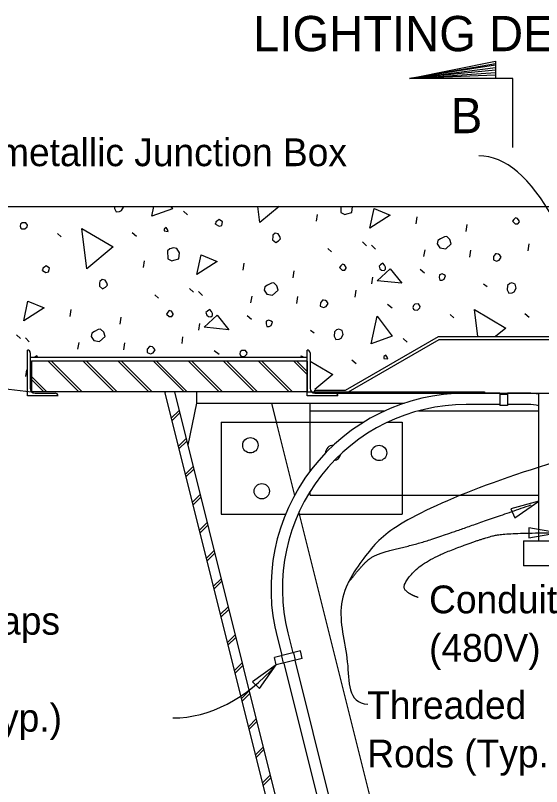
# Model space of a CAD drawing. Extents: x 112544 to 112597.1, y 111084 to 111107.1.
# Drawn here: x 112545.622 to 112548.485, y 111091.281 to 111095.48 of the extents above; entities that cross this region are included whole.
import ezdxf

# ---------------------------------------------------------------- set-up
doc = ezdxf.new("R2010")
doc.units = 0
for name, color, linetype in [('Dimension', 7, 'Continuous'), ('Lighting', 7, 'Continuous'), ('Miscellaneous', 7, 'Continuous'), ('SteelGirder', 7, 'Continuous'), ('SteelGirder_h', 7, 'Continuous'), ('SupstrConc', 7, 'Continuous'), ('TextStructures', 7, 'Continuous')]:
    doc.layers.add(name, color=color, linetype=linetype)

msp = doc.modelspace()

# ---------------------------------------------------------------- linework, layer by layer
at = {"layer": 'Dimension'}
for p, q in [((112547.7665, 111095.1362), (112548.2352, 111095.2187)), ((112548.2352, 111095.2087), (112547.7665, 111095.1362)), ((112547.7665, 111095.1362), (112548.2352, 111095.1962)), ((112548.2352, 111095.1824), (112547.7665, 111095.1362)), ((112547.7665, 111095.1362), (112548.2352, 111095.1687)), ((112548.2352, 111095.1537), (112547.7665, 111095.1362))]:
    msp.add_line(p, q, dxfattribs=at)
msp.add_lwpolyline([(112548.3289, 111094.7612), (112548.3289, 111095.1362), (112547.7665, 111095.1362), (112548.2352, 111095.2299), (112548.2352, 111095.1362)], dxfattribs=at)
for points in [[(112548.4699, 111092.8343), (112548.317, 111092.7931), (112548.3391, 111092.745)], [(112548.5722, 111092.6627), (112548.416, 111092.6892), (112548.416, 111092.6362)], [(112547.0411, 111091.9439), (112546.9118, 111091.8524), (112546.9491, 111091.8149)]]:
    msp.add_lwpolyline(points, close=True, dxfattribs=at)
for centre, major_axis, ratio, start_param, end_param in [((112548.1769, 111092.198), (0.0332, -2.5173), 0.313255, 2.075166, 3.141607), ((112546.4637, 111093.2488), (-0.0144, 1.5941), 0.622544, 3.141613, 3.747853)]:
    msp.add_ellipse(centre, major_axis=major_axis, ratio=ratio, start_param=start_param, end_param=end_param, dxfattribs=at)
for points, degree in [([(112548.9701, 111093.1717), (112548.6743, 111093.0852), (112548.1844, 111092.9372), (112547.674, 111092.7074), (112547.5362, 111092.5593), (112547.3473, 111092.2836), (112547.4514, 111091.9614), (112547.4271, 111091.7394), (112547.5394, 111091.7292)], 3), ([(112547.4342, 111092.3931), (112547.5004, 111092.4776), (112547.577, 111092.5491), (112547.8271, 111092.6053), (112548.0874, 111092.6972), (112548.4279, 111092.8149)], 2), ([(112547.8143, 111092.3104), (112547.7556, 111092.3308), (112547.725, 111092.3819), (112547.85, 111092.5146), (112548.1741, 111092.6372), (112548.2992, 111092.6627), (112548.5722, 111092.6627)], 2), ([(112546.6152, 111090.8361), (112548.0879, 111090.8463), (112549.0316, 111090.8974), (112549.0112, 111091.3926), (112548.9755, 111092.3627)], 2)]:
    msp.add_open_spline(points, degree=degree, dxfattribs=at)
at = {"layer": 'Lighting'}
for p, q in [((112548.2588, 111093.4236), (112548.0748, 111093.4236)), ((112548.4112, 111093.4236), (112548.3005, 111093.4236)), ((112548.2588, 111093.3611), (112548.0748, 111093.3611)), ((112548.4115, 111093.3611), (112548.3005, 111093.3611)), ((112548.3866, 111092.6185), (112549.0845, 111092.6185)), ((112548.3866, 111092.6185), (112548.3866, 111092.4831)), ((112548.5971, 111092.4831), (112548.3866, 111092.4831)), ((112547.0475, 111092.0902), (112547.0714, 111091.9945)), ((112547.1047, 111092.1186), (112547.1319, 111092.0096)), ((112547.0815, 111091.954), (112547.5799, 111089.9602)), ((112547.142, 111091.9692), (112547.6405, 111089.9754))]:
    msp.add_line(p, q, dxfattribs=at)
for centre, radius, start, end in [((112548.0748, 111092.3611), 1.0625, 90.0002, 194.7729), ((112548.4109, 111093.1111), 0.3125, 79.1097, 89.9466), ((112548.0748, 111092.3611), 1, 90.0002, 194.0354), ((112548.4109, 111093.1111), 0.25, 76.3399, 89.8674)]:
    msp.add_arc(centre, radius, start, end, dxfattribs=at)
at = {"layer": 'Miscellaneous'}
for p, q in [((112546.5366, 111094.4148), (112546.5576, 111094.3946)), ((112547.2604, 111094.3603), (112547.2665, 111094.3956)), ((112547.8028, 111094.3452), (112547.8082, 111094.3829)), ((112548.0752, 111094.3043), (112548.0806, 111094.342)), ((112545.8498, 111094.2929), (112545.8701, 111094.2751)), ((112546.2572, 111094.2986), (112546.2806, 111094.2789)), ((112547.511, 111094.2463), (112547.5319, 111094.226)), ((112547.5598, 111094.2283), (112547.5807, 111094.208)), ((112548.4117, 111094.1978), (112548.4171, 111094.2354)), ((112547.3211, 111094.2109), (112547.3414, 111094.1931)), ((112547.8452, 111094.1676), (112547.8513, 111094.2029)), ((112548.0945, 111094.1645), (112548.0999, 111094.2022)), ((112546.3186, 111094.108), (112546.3247, 111094.1432)), ((112546.861, 111094.0928), (112546.8665, 111094.1305)), ((112547.8252, 111094.0975), (112547.8485, 111094.0779)), ((112547.1334, 111094.0519), (112547.1388, 111094.0896)), ((112547.5615, 111094.0191), (112547.5675, 111094.0544)), ((112548.1697, 111094.019), (112548.1894, 111094.0036)), ((112546.5692, 111093.9939), (112546.5901, 111093.9737)), ((112546.618, 111093.9759), (112546.639, 111093.9557)), ((112547.4699, 111093.9454), (112547.4754, 111093.9831)), ((112546.3794, 111093.9586), (112546.3997, 111093.9407)), ((112546.9034, 111093.9153), (112546.9095, 111093.9505)), ((112547.1527, 111093.9122), (112547.1582, 111093.9499)), ((112547.6458, 111093.9071), (112547.6716, 111093.8882)), ((112545.9192, 111093.8405), (112545.9247, 111093.8782)), ((112546.8834, 111093.8452), (112546.9068, 111093.8256)), ((112547.987, 111093.851), (112548.0073, 111093.8332)), ((112548.3944, 111093.8566), (112548.4178, 111093.837)), ((112546.1916, 111093.7996), (112546.197, 111093.8373)), ((112546.6197, 111093.7668), (112546.6258, 111093.802)), ((112547.2279, 111093.7667), (112547.2476, 111093.7512)), ((112545.6274, 111093.7416), (112545.6484, 111093.7213)), ((112545.6762, 111093.7236), (112545.6972, 111093.7033)), ((112546.5282, 111093.6931), (112546.5336, 111093.7307)), ((112547.4182, 111093.4392), (112547.9235, 111093.7309)), ((112547.732, 111093.7206), (112547.753, 111093.7003)), ((112547.9235, 111093.7309), (112552.7436, 111093.7309)), ((112545.9617, 111093.6629), (112545.9677, 111093.6982)), ((112546.2109, 111093.6598), (112546.2164, 111093.6975)), ((112547.4224, 111093.4236), (112547.9277, 111093.7153)), ((112547.9277, 111093.7153), (112552.7436, 111093.7153)), ((112545.6866, 111093.4079), (112545.6866, 111093.6579)), ((112545.7022, 111093.6423), (112545.7022, 111093.4496)), ((112546.7041, 111093.6548), (112546.7298, 111093.6358)), ((112547.2099, 111093.408), (112547.2099, 111093.658)), ((112547.2256, 111093.6423), (112547.2255, 111093.4496)), ((112545.7023, 111093.6187), (112547.2099, 111093.6187)), ((112545.7023, 111093.5979), (112545.7099, 111093.5979)), ((112545.9664, 111093.4312), (112545.7997, 111093.5979)), ((112545.9841, 111093.4312), (112545.8173, 111093.5979)), ((112546.1573, 111093.4312), (112545.9906, 111093.5979)), ((112546.175, 111093.4312), (112546.0083, 111093.5979)), ((112546.3482, 111093.4312), (112546.1815, 111093.5979)), ((112546.3659, 111093.4312), (112546.1992, 111093.5979)), ((112546.5391, 111093.4312), (112546.3724, 111093.5979)), ((112546.5568, 111093.4312), (112546.3901, 111093.5979)), ((112546.7301, 111093.4312), (112546.5633, 111093.5979)), ((112546.7477, 111093.4312), (112546.581, 111093.5979)), ((112546.921, 111093.4312), (112546.7543, 111093.5979)), ((112546.9387, 111093.4312), (112546.7719, 111093.5979)), ((112547.1119, 111093.4312), (112546.9452, 111093.5979)), ((112547.1296, 111093.4312), (112546.9629, 111093.5979)), ((112547.2099, 111093.5241), (112547.1361, 111093.5979)), ((112547.2099, 111093.5418), (112547.1538, 111093.5979)), ((112547.4526, 111093.6043), (112547.476, 111093.5847)), ((112545.6779, 111093.5144), (112545.684, 111093.5497)), ((112545.7931, 111093.4312), (112545.7099, 111093.5144)), ((112545.7755, 111093.4312), (112545.7099, 111093.4968)), ((112545.7283, 111093.4235), (112545.8376, 111093.4235)), ((112546.4345, 111093.425), (112546.4407, 111093.4311)), ((112547.2516, 111093.4392), (112547.4182, 111093.4392)), ((112547.2516, 111093.4236), (112547.2516, 111093.4392)), ((112547.2516, 111093.4236), (112547.361, 111093.4236)), ((112547.2516, 111093.4236), (112552.7436, 111093.4236)), ((112545.8533, 111093.4079), (112545.6866, 111093.4079)), ((112547.3766, 111093.4079), (112547.2099, 111093.408)), ((112546.4692, 111093.2864), (112546.5121, 111093.3294)), ((112546.4727, 111093.2723), (112546.5157, 111093.3153)), ((112546.5074, 111093.1337), (112546.5503, 111093.1767)), ((112546.5109, 111093.1196), (112546.5539, 111093.1625)), ((112546.5456, 111092.981), (112546.5885, 111093.0239)), ((112546.5491, 111092.9668), (112546.5921, 111093.0098)), ((112546.5837, 111092.8282), (112546.6267, 111092.8712)), ((112546.5873, 111092.8141), (112546.6302, 111092.857)), ((112546.6219, 111092.6755), (112546.6649, 111092.7185)), ((112546.6255, 111092.6613), (112546.6684, 111092.7043)), ((112546.6601, 111092.5228), (112546.7031, 111092.5657)), ((112546.6636, 111092.5086), (112546.7066, 111092.5516)), ((112546.6983, 111092.37), (112546.7412, 111092.413)), ((112546.7018, 111092.3559), (112546.7448, 111092.3988)), ((112546.7365, 111092.2173), (112546.7794, 111092.2602)), ((112546.74, 111092.2031), (112546.783, 111092.2461)), ((112546.7747, 111092.0645), (112546.8176, 111092.1075)), ((112546.7782, 111092.0504), (112546.8212, 111092.0934)), ((112546.8128, 111091.9118), (112546.8558, 111091.9548)), ((112546.8164, 111091.8977), (112546.8593, 111091.9406)), ((112546.851, 111091.7591), (112546.894, 111091.802)), ((112546.8546, 111091.7449), (112546.8975, 111091.7879)), ((112546.8892, 111091.6063), (112546.9322, 111091.6493)), ((112546.8927, 111091.5922), (112546.9357, 111091.6352)), ((112546.9274, 111091.4536), (112546.9704, 111091.4966)), ((112546.9309, 111091.4395), (112546.9739, 111091.4824)), ((112546.9656, 111091.3009), (112547.0085, 111091.3438)), ((112546.9691, 111091.2867), (112547.0121, 111091.3297))]:
    msp.add_line(p, q, dxfattribs=at)
for points in [[(112546.1611, 111094.4392), (112546.1604, 111094.4279), (112546.1704, 111094.4099), (112546.188, 111094.412), (112546.1994, 111094.4177), (112546.21, 111094.436), (112546.2092, 111094.4392)], [(112546.3631, 111094.3865), (112546.3742, 111094.4392)], [(112546.4675, 111094.4392), (112546.4764, 111094.4272), (112546.3631, 111094.3865)], [(112546.9519, 111094.3527), (112546.9409, 111094.4392)], [(112547.0567, 111094.4392), (112546.9519, 111094.3527)], [(112547.392, 111094.4392), (112547.393, 111094.4062), (112547.4138, 111094.3962), (112547.4259, 111094.3995), (112547.4525, 111094.4066), (112547.4568, 111094.4388), (112547.4566, 111094.4392)], [(112547.5503, 111094.3215), (112547.5734, 111094.4286), (112547.6607, 111094.3925), (112547.5503, 111094.3215)], [(112545.6504, 111094.3223), (112545.6565, 111094.3188), (112545.6723, 111094.3178), (112545.6848, 111094.329), (112545.6877, 111094.3375), (112545.679, 111094.3507), (112545.6584, 111094.3503), (112545.65, 111094.3429), (112545.6478, 111094.332), (112545.6504, 111094.3223)], [(112546.7113, 111094.3426), (112546.7297, 111094.332), (112546.7441, 111094.3359), (112546.7493, 111094.3554), (112546.7303, 111094.3684), (112546.7219, 111094.361), (112546.7129, 111094.356), (112546.7113, 111094.3426), (112546.71, 111094.3474)], [(112548.3271, 111094.3589), (112548.3413, 111094.3445), (112548.3565, 111094.346), (112548.3642, 111094.3558), (112548.3629, 111094.3607), (112548.3542, 111094.3739), (112548.3426, 111094.3785), (112548.3348, 111094.3687), (112548.3271, 111094.3589)], [(112546.0101, 111094.1003), (112545.9821, 111094.3206), (112546.1542, 111094.2192), (112546.0101, 111094.1003)], [(112546.4311, 111094.3063), (112546.4524, 111094.3043), (112546.4498, 111094.3139), (112546.4417, 111094.3247), (112546.4309, 111094.3166), (112546.4311, 111094.3063)], [(112547.0217, 111094.2756), (112547.0214, 111094.2574), (112547.038, 111094.2438), (112547.0536, 111094.2531), (112547.0637, 111094.2636), (112547.0605, 111094.2757), (112547.0511, 111094.2913), (112547.0347, 111094.2947), (112547.0222, 111094.2835), (112547.0217, 111094.2756)], [(112547.9174, 111094.2361), (112547.9311, 111094.2139), (112547.9634, 111094.2096), (112547.9926, 111094.2356), (112547.9862, 111094.2597), (112547.9689, 111094.2758), (112547.9562, 111094.275), (112547.9358, 111094.2643), (112547.9201, 111094.255), (112547.9174, 111094.2361)], [(112546.4499, 111094.1975), (112546.4513, 111094.1539), (112546.4721, 111094.1439), (112546.4841, 111094.1471), (112546.5107, 111094.1542), (112546.515, 111094.1865), (112546.5006, 111094.2111), (112546.4818, 111094.2138), (112546.4625, 111094.2086), (112546.4499, 111094.1975)], [(112548.223, 111094.1679), (112548.2227, 111094.1497), (112548.2404, 111094.1415), (112548.2543, 111094.1478), (112548.2655, 111094.1638), (112548.2575, 111094.1745), (112548.2507, 111094.1805), (112548.2397, 111094.1827), (112548.2349, 111094.1814), (112548.223, 111094.1679)], [(112546.6085, 111094.0692), (112546.6316, 111094.1763), (112546.7189, 111094.1402), (112546.6085, 111094.0692)], [(112545.7695, 111094.0902), (112545.7879, 111094.0796), (112545.8024, 111094.0835), (112545.8075, 111094.103), (112545.7885, 111094.116), (112545.7801, 111094.1086), (112545.7711, 111094.1036), (112545.7695, 111094.0902), (112545.7682, 111094.0951)], [(112547.3854, 111094.1065), (112547.3995, 111094.0922), (112547.4147, 111094.0937), (112547.4224, 111094.1035), (112547.4211, 111094.1083), (112547.4124, 111094.1215), (112547.4008, 111094.1262), (112547.3931, 111094.1163), (112547.3854, 111094.1065)], [(112547.5909, 111094.0348), (112547.6614, 111094.1002), (112547.724, 111094.0212), (112547.5909, 111094.0348)], [(112547.6044, 111094.1005), (112547.6142, 111094.0928), (112547.6276, 111094.0912), (112547.6359, 111094.0986), (112547.6358, 111094.1089), (112547.6301, 111094.1203), (112547.622, 111094.1311), (112547.6089, 111094.1224), (112547.6005, 111094.115), (112547.6044, 111094.1005)], [(112547.9278, 111094.0526), (112547.9317, 111094.0381), (112547.9444, 111094.0389), (112547.9558, 111094.0445), (112547.9616, 111094.0616), (112547.9548, 111094.0676), (112547.9432, 111094.0722), (112547.9287, 111094.0683), (112547.9278, 111094.0526)], [(112546.0799, 111094.0233), (112546.0796, 111094.0051), (112546.0962, 111093.9914), (112546.1118, 111094.0008), (112546.122, 111094.0113), (112546.1187, 111094.0233), (112546.1094, 111094.0389), (112546.0929, 111094.0423), (112546.0804, 111094.0312), (112546.0799, 111094.0233)], [(112546.9757, 111093.9838), (112546.9894, 111093.9616), (112547.0216, 111093.9573), (112547.0509, 111093.9832), (112547.0444, 111094.0074), (112547.0271, 111094.0235), (112547.0144, 111094.0226), (112546.994, 111094.012), (112546.9784, 111094.0026), (112546.9757, 111093.9838)], [(112548.299, 111094.0097), (112548.2976, 111093.986), (112548.3076, 111093.968), (112548.3252, 111093.9701), (112548.3366, 111093.9757), (112548.3472, 111093.9941), (112548.3414, 111094.0159), (112548.3237, 111094.024), (112548.3116, 111094.0208), (112548.299, 111094.0097)], [(112547.2812, 111093.9155), (112547.2809, 111093.8973), (112547.2987, 111093.8892), (112547.3125, 111093.8955), (112547.3237, 111093.9114), (112547.3157, 111093.9222), (112547.3089, 111093.9281), (112547.298, 111093.9304), (112547.2931, 111093.9291), (112547.2812, 111093.9155)], [(112545.6668, 111093.8168), (112545.6898, 111093.9239), (112545.7772, 111093.8878), (112545.6668, 111093.8168)], [(112547.7876, 111093.8804), (112547.7937, 111093.8769), (112547.8095, 111093.8759), (112547.822, 111093.887), (112547.8249, 111093.8956), (112547.8162, 111093.9088), (112547.7956, 111093.9084), (112547.7872, 111093.901), (112547.785, 111093.8901), (112547.7876, 111093.8804)], [(112546.4436, 111093.8542), (112546.4578, 111093.8398), (112546.4729, 111093.8413), (112546.4806, 111093.8511), (112546.4793, 111093.856), (112546.4706, 111093.8692), (112546.459, 111093.8738), (112546.4513, 111093.864), (112546.4436, 111093.8542)], [(112546.6491, 111093.7824), (112546.7196, 111093.8479), (112546.7822, 111093.7689), (112546.6491, 111093.7824)], [(112546.6626, 111093.8481), (112546.6724, 111093.8404), (112546.6858, 111093.8388), (112546.6942, 111093.8462), (112546.694, 111093.8565), (112546.6883, 111093.868), (112546.6803, 111093.8788), (112546.6671, 111093.87), (112546.6587, 111093.8626), (112546.6626, 111093.8481)], [(112547.5585, 111093.6922), (112547.5905, 111093.8431), (112547.6718, 111093.7329), (112547.5585, 111093.6922)], [(112548.1381, 111093.7309), (112548.1193, 111093.8787), (112548.2914, 111093.7773), (112548.2351, 111093.7309)], [(112546.986, 111093.8002), (112546.9899, 111093.7857), (112547.0026, 111093.7865), (112547.014, 111093.7922), (112547.0198, 111093.8093), (112547.0131, 111093.8152), (112547.0015, 111093.8199), (112546.987, 111093.816), (112546.986, 111093.8002)], [(112546.0339, 111093.7314), (112546.0476, 111093.7092), (112546.0798, 111093.7049), (112546.1091, 111093.7309), (112546.1026, 111093.755), (112546.0854, 111093.7711), (112546.0726, 111093.7703), (112546.0522, 111093.7596), (112546.0366, 111093.7503), (112546.0339, 111093.7314)], [(112547.3573, 111093.7573), (112547.3558, 111093.7337), (112547.3659, 111093.7156), (112547.3834, 111093.7178), (112547.3948, 111093.7234), (112547.4054, 111093.7418), (112547.3996, 111093.7635), (112547.3819, 111093.7717), (112547.3698, 111093.7685), (112547.3573, 111093.7573)], [(112546.3394, 111093.6632), (112546.3391, 111093.645), (112546.3569, 111093.6368), (112546.3707, 111093.6431), (112546.382, 111093.6591), (112546.3739, 111093.6698), (112546.3671, 111093.6758), (112546.3562, 111093.678), (112546.3513, 111093.6767), (112546.3394, 111093.6632)], [(112546.8458, 111093.6281), (112546.8519, 111093.6245), (112546.8677, 111093.6236), (112546.8803, 111093.6347), (112546.8831, 111093.6432), (112546.8744, 111093.6564), (112546.8538, 111093.6561), (112546.8455, 111093.6487), (112546.8432, 111093.6377), (112546.8458, 111093.6281)], [(112545.7443, 111093.6187), (112545.7385, 111093.6264), (112545.7268, 111093.6187)], [(112547.1785, 111093.6187), (112547.1775, 111093.6264), (112547.1906, 111093.6187)], [(112547.2256, 111093.5981), (112547.3497, 111093.5249), (112547.2506, 111093.4433)], [(112547.6265, 111093.6121), (112547.6478, 111093.61), (112547.6452, 111093.6197), (112547.6371, 111093.6304), (112547.6264, 111093.6224), (112547.6265, 111093.6121)]]:
    msp.add_lwpolyline(points, dxfattribs=at)
for centre, radius, start, end in [((112545.6866, 111093.6423), 0.0156, 359.9953, 89.9953), ((112547.2099, 111093.6423), 0.0156, 359.9953, 89.9953), ((112545.7283, 111093.4496), 0.026, 179.9953, 269.9953), ((112545.8376, 111093.4079), 0.0156, 359.9953, 89.9953), ((112547.2516, 111093.4496), 0.026, 179.9953, 269.9953), ((112547.361, 111093.4079), 0.0156, 359.9953, 89.9953)]:
    msp.add_arc(centre, radius, start, end, dxfattribs=at)
at = {"layer": 'SteelGirder'}
for p, q in [((112545.7099, 111093.5979), (112545.7099, 111093.4311)), ((112547.2099, 111093.5979), (112545.7099, 111093.5979)), ((112547.2099, 111093.5979), (112547.2099, 111093.4311)), ((112547.2099, 111093.4311), (112545.7099, 111093.4311)), ((112546.433, 111093.4311), (112547.9955, 111087.1812)), ((112546.4867, 111093.4311), (112548.0492, 111087.1812)), ((112546.6085, 111093.3686), (112546.6085, 111093.4311)), ((112547.2073, 111093.4311), (112547.2099, 111093.4338)), ((112547.2073, 111093.4311), (112547.2099, 111093.4338)), ((112547.2099, 111093.4311), (112548.1744, 111093.4311)), ((112548.1744, 111093.4311), (112548.1744, 111093.4236)), ((112548.2588, 111093.4236), (112548.2588, 111093.3559)), ((112548.2588, 111093.4236), (112548.3005, 111093.4236)), ((112548.3005, 111093.4236), (112548.3005, 111093.3559)), ((112548.4699, 111092.6185), (112548.4699, 111093.4236)), ((112548.2588, 111093.4184), (112548.3005, 111093.4184)), ((112546.6064, 111093.3686), (112546.5593, 111093.1408)), ((112546.6085, 111093.3686), (112547.7375, 111093.3686)), ((112547.0146, 111093.3686), (112547.0406, 111093.2644)), ((112547.2255, 111093.254), (112547.2255, 111093.3686)), ((112548.3005, 111093.3559), (112548.2588, 111093.3559)), ((112547.2255, 111093.3269), (112547.6321, 111093.3269)), ((112547.8157, 111093.3269), (112548.4699, 111093.3269)), ((112546.7412, 111093.2644), (112546.7412, 111092.7644)), ((112546.7412, 111093.2644), (112547.5155, 111093.2644)), ((112547.6459, 111093.2644), (112547.7255, 111093.2644)), ((112547.7255, 111093.2644), (112547.7255, 111092.7644)), ((112547.7255, 111092.8685), (112548.4699, 111092.8685)), ((112546.7412, 111092.7644), (112547.0919, 111092.7644)), ((112547.1598, 111092.7644), (112547.7255, 111092.7644)), ((112547.1656, 111092.7644), (112548.1528, 111088.8165)), ((112547.1724, 111092.0197), (112547.0309, 111091.9844)), ((112547.1342, 111092.0102), (112547.1443, 111091.9697)), ((112547.1825, 111091.9793), (112547.1724, 111092.0197)), ((112547.0411, 111091.9439), (112547.0309, 111091.9844)), ((112547.1825, 111091.9793), (112547.0411, 111091.9439)), ((112547.0692, 111091.9939), (112547.0793, 111091.9535))]:
    msp.add_line(p, q, dxfattribs=at)
for centre in [(112546.9001, 111093.1394), (112547.6005, 111093.0977), (112546.9626, 111092.8894)]:
    msp.add_circle(centre, 0.0417, dxfattribs=at)
for start, end in [(88.5209, 180.5137), (277.7816, 351.253)]:
    msp.add_arc((112547.3505, 111093.0977), 0.0417, start, end, dxfattribs=at)
at = {"layer": 'SteelGirder_h'}
for p, q in [((112547.2255, 111092.9995), (112547.2255, 111093.3269)), ((112547.0406, 111093.2644), (112547.1402, 111092.8664)), ((112547.2255, 111092.8685), (112547.2255, 111092.8889)), ((112547.2255, 111092.8685), (112547.7255, 111092.8685)), ((112547.1636, 111092.7729), (112547.1657, 111092.7644))]:
    msp.add_line(p, q, dxfattribs=at)
at = {"layer": 'SupstrConc'}
for p, q in [((112544.2555, 111094.4392), (112552.7436, 111094.4392)), ((112544.2555, 111093.5963), (112545.7099, 111093.4312))]:
    msp.add_line(p, q, dxfattribs=at)

# ---------------------------------------------------------------- texts
at = {"layer": 'Dimension'}
for s, p in [('Conduit', (112547.8729, 111092.2247)), ('Single hole straps', (112544.257, 111092.1083)), ('(480V)', (112547.8729, 111091.9607)), ('Threaded', (112547.5362, 111091.6494)), ('(see Note 8, Typ.)', (112544.257, 111091.5803)), ('Rods (Typ.)', (112547.5362, 111091.3854))]:
    msp.add_text(s, height=0.1512, dxfattribs=at).set_placement(p)
at = {"layer": 'TextStructures'}
for s, height, p in [('LIGHTING DETAILS FOR CONCRETE BOX GIRDER BRIDGE', 0.192, (112546.9154, 111095.285)), ('B', 0.192, (112547.9915, 111094.8385)), ('Nonmetallic Junction Box', 0.1512, (112545.1559, 111094.6591))]:
    msp.add_text(s, height=height, dxfattribs=at).set_placement(p)

doc.saveas('drawing.dxf')
